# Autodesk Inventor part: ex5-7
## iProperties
Shininess: 64.0
Length Units: 11272
Angle Units: 11279
Time Units: 11290
Mass Units: 11286
Length Display Precision: 3
Angle Display Precision: 2
Compacted: True
Part Number: ex5-7
Document SubType Name: Modeling
Created: 2002-09
Designer: Elise Moss
Density: 0.0
Volumn: 0.0
Area: 0.0
PropertySet Name: Model Information
Control State: 0
Master: False
Checked Out: False
Author: Elise Moss
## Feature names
1. Revolution1
2. Hole1
3. Shell1
4. Loft1
5. Sweep1
